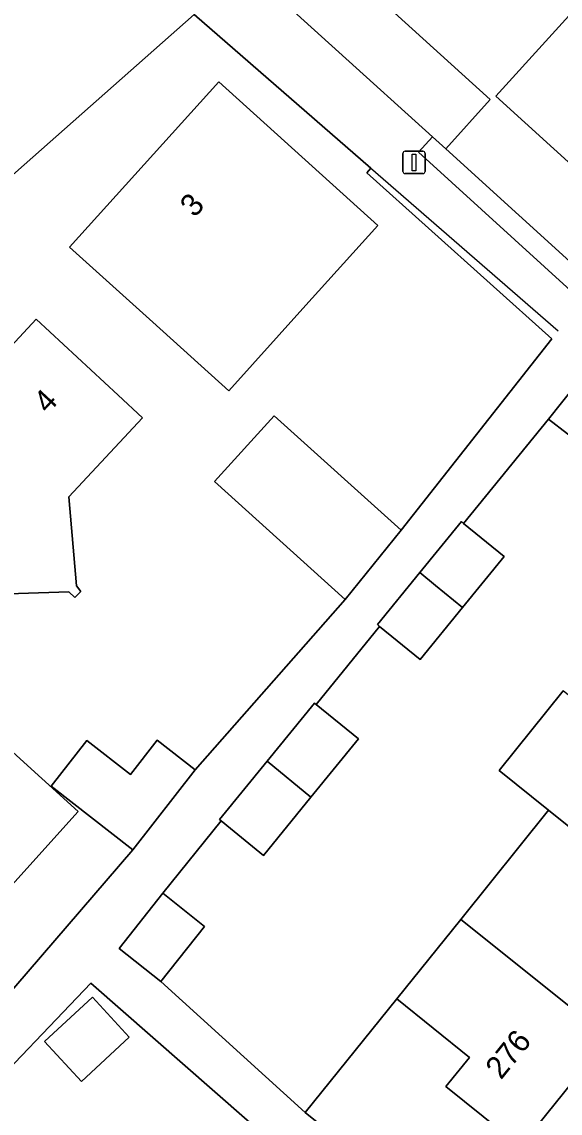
# Model space of a CAD drawing. Extents: x 158472 to 159562, y 388525 to 389606.
# Drawn here: x 158642.99 to 158667.04, y 388899.14 to 388947.87 of the extents above; entities that cross this region are included whole.
import ezdxf

# ---------------------------------------------------------------- set-up
doc = ezdxf.new("R2010")
doc.units = 0
for name, color, linetype in [('IMGEO_Erf', 7, 'Continuous'), ('IMGEO_Groenvoorziening', 7, 'Continuous'), ('IMGEO_Lichtmast', 7, 'Continuous'), ('IMGEO_Muur', 7, 'Continuous'), ('IMGEO_Pand', 7, 'Continuous'), ('IMGEO_Pand_nummerreeks', 7, 'Continuous'), ('IMGEO_Rijbaan_lokaal_open', 7, 'Continuous'), ('IMGEO_Voetpad_open', 7, 'Continuous')]:
    doc.layers.add(name, color=color, linetype=linetype)

msp = doc.modelspace()

# ---------------------------------------------------------------- linework, layer by layer
at = {"layer": 'IMGEO_Erf'}
for points in [[(158668.747, 388949.605), (158664.165, 388944.557), (158670.641, 388938.679), (158697.972, 388974.859)], [(158652.977, 388950.312), (158661.333, 388942.738), (158661.926, 388942.201), (158663.919, 388944.397), (158657.904, 388949.857)], [(158641.527, 388903.446), (158647.946, 388910.907), (158644.303, 388913.751), (158645.893, 388915.788), (158647.842, 388914.266), (158649.035, 388915.794), (158650.729, 388914.472), (158657.439, 388922.083), (158651.607, 388927.344), (158654.26, 388930.285), (158659.932, 388925.168), (158666.666, 388933.718), (158658.402, 388941.12), (158658.589, 388941.335), (158650.686, 388948.203), (158630.856, 388930.685)], [(158668.212, 388928.813), (158666.516, 388930.132), (158662.722, 388925.476), (158664.538, 388923.998), (158662.68, 388921.72), (158660.779, 388919.399), (158658.972, 388920.879), (158656.135, 388917.397), (158658.026, 388915.853), (158655.908, 388913.258), (158653.785, 388910.653), (158652.317, 388911.852), (158651.898, 388912.195), (158649.288, 388908.962), (158651.153, 388907.486), (158649.202, 388905.02), (158655.653, 388899.181), (158659.741, 388904.253), (158662.596, 388907.797), (158666.523, 388912.669), (158664.32, 388914.445), (158667.18, 388917.994)], [(158681.727, 388907.247), (158688.881, 388916.431), (158683.73, 388920.567), (158681.495, 388917.794), (158682.74, 388916.779), (158679.952, 388913.298), (158678.687, 388914.31), (158677.464, 388912.792), (158678.711, 388911.788), (158677.223, 388909.942), (158675.571, 388907.892), (158674.328, 388908.894), (158672.051, 388906.068), (158670.706, 388904.398), (158671.908, 388903.429), (158670.402, 388901.56), (158668.766, 388899.53), (158667.556, 388900.505), (158665.263, 388897.66), (158663.911, 388895.983), (158665.126, 388895.004), (158663.438, 388892.908), (158667.216, 388889.629)], [(158641.567, 388888.565), (158644.692, 388891.853), (158645.314, 388891.262), (158648.801, 388894.93), (158650.361, 388893.447), (158651.174, 388894.299), (158654.39, 388897.669), (158646.076, 388904.95), (158640.8, 388899.447)]]:
    msp.add_lwpolyline(points, dxfattribs=at)
for points in [[(158651.788, 388945.187), (158658.897, 388938.775), (158655.548, 388935.063), (158652.238, 388931.393), (158648.843, 388934.456), (158645.13, 388937.805)], [(158643.635, 388934.6), (158647.3, 388931.199), (158648.382, 388930.194), (158645.098, 388926.657), (158645.433, 388922.691), (158645.624, 388922.437), (158645.357, 388922.17), (158645.09, 388922.424), (158639.224, 388922.223), (158636.672, 388924.688), (158636.24, 388930.403), (158635.935, 388930.695), (158636.151, 388930.987), (158636.468, 388930.67), (158640.24, 388930.943)], [(158627.039, 388914.369), (158626.648, 388914.972), (158632.647, 388918.937), (158635.289, 388921.857), (158638.997, 388918.503), (158645.513, 388912.607), (158640.255, 388906.796), (158639.615, 388907.375), (158638.527, 388905.932), (158630.624, 388906.451), (158630.151, 388907.075), (158629.427, 388906.606), (158627.724, 388909.233), (158626.037, 388908.14), (158623.49, 388912.069)], [(158645.66, 388900.564), (158644.013, 388902.345), (158646.148, 388904.318), (158647.794, 388902.538)]]:
    msp.add_lwpolyline(points, close=True, dxfattribs=at)
at = {"layer": 'IMGEO_Groenvoorziening'}
msp.add_lwpolyline([(158661.926, 388942.201), (158661.333, 388942.738), (158660.708, 388942.048), (158667.83, 388935.583), (158668.457, 388936.273)], close=True, dxfattribs=at)
at = {"layer": 'IMGEO_Lichtmast'}
for p, q in [((158660.016, 388941.191), (158660.016, 388941.991)), ((158660.016, 388941.991), (158660.016, 388941.191)), ((158660.116, 388942.091), (158660.906, 388942.091)), ((158660.906, 388942.091), (158660.116, 388942.091)), ((158661.006, 388941.991), (158661.006, 388941.191)), ((158661.006, 388941.191), (158661.006, 388941.991)), ((158660.906, 388941.091), (158660.116, 388941.091)), ((158660.116, 388941.091), (158660.906, 388941.091))]:
    msp.add_line(p, q, dxfattribs=at)
msp.add_lwpolyline([(158660.436, 388941.966), (158660.586, 388941.966), (158660.586, 388941.216), (158660.436, 388941.216), (158660.436, 388941.966)], dxfattribs=at)
for centre, start, end in [((158660.116, 388941.991), 90, 180), ((158660.116, 388941.991), 90, 180), ((158660.906, 388941.991), 0, 90), ((158660.906, 388941.991), 360, 90), ((158660.116, 388941.191), 180, 270), ((158660.116, 388941.191), 180, 270), ((158660.906, 388941.191), 270, 0), ((158660.906, 388941.191), 270, 0)]:
    msp.add_arc(centre, 0.1, start, end, dxfattribs=at)
at = {"layer": 'IMGEO_Muur'}
msp.add_lwpolyline([(158658.566, 388941.355), (158666.945, 388934.072)], dxfattribs=at)
at = {"layer": 'IMGEO_Pand'}
for points in [[(158666.506, 388954.788), (158670.581, 388956.54), (158670.265, 388957.284), (158677.436, 388960.255), (158674.656, 388966.964), (158674.547, 388966.919), (158671.398, 388965.614), (158669.563, 388964.853), (158670.912, 388961.598), (158668.806, 388960.726), (158667.431, 388963.97), (158658.929, 388960.447), (158654.309, 388958.532), (158657.904, 388949.857), (158663.919, 388944.397), (158661.926, 388942.201), (158668.457, 388936.273), (158670.641, 388938.679), (158664.165, 388944.557), (158668.747, 388949.605)], [(158648.843, 388934.456), (158652.238, 388931.393), (158655.548, 388935.063), (158658.897, 388938.775), (158651.788, 388945.187), (158645.13, 388937.805)], [(158647.3, 388931.199), (158643.635, 388934.6), (158640.24, 388930.943), (158636.468, 388930.67), (158636.151, 388930.987), (158635.935, 388930.695), (158636.24, 388930.403), (158636.672, 388924.688), (158639.224, 388922.223), (158645.09, 388922.424), (158645.357, 388922.17), (158645.624, 388922.437), (158645.433, 388922.691), (158645.098, 388926.657), (158648.382, 388930.194)], [(158670.255, 388931.362), (158668.546, 388932.681), (158668.32, 388932.398), (158666.516, 388930.132), (158668.212, 388928.813)], [(158657.439, 388922.083), (158659.932, 388925.168), (158654.26, 388930.285), (158651.607, 388927.344)], [(158662.722, 388925.476), (158662.627, 388925.554), (158660.775, 388923.28), (158661.473, 388922.709), (158662.68, 388921.72), (158664.538, 388923.998)], [(158662.68, 388921.72), (158661.473, 388922.709), (158660.775, 388923.28), (158658.874, 388920.959), (158658.972, 388920.879), (158660.779, 388919.399)], [(158629.427, 388906.606), (158630.151, 388907.075), (158630.624, 388906.451), (158638.527, 388905.932), (158639.615, 388907.375), (158640.255, 388906.796), (158645.513, 388912.607), (158638.997, 388918.503), (158635.289, 388921.857), (158632.647, 388918.937), (158626.648, 388914.972), (158627.039, 388914.369), (158623.49, 388912.069), (158626.037, 388908.14), (158627.724, 388909.233)], [(158666.523, 388912.669), (158669.78, 388910.05), (158668.73, 388908.75), (158672.051, 388906.068), (158674.328, 388908.894), (158675.571, 388907.892), (158677.223, 388909.942), (158667.18, 388917.994), (158664.32, 388914.445)], [(158656.135, 388917.397), (158656.069, 388917.45), (158653.951, 388914.855), (158655.908, 388913.258), (158658.026, 388915.853)], [(158650.729, 388914.472), (158649.035, 388915.794), (158647.842, 388914.266), (158645.893, 388915.788), (158644.303, 388913.751), (158647.946, 388910.907)], [(158655.908, 388913.258), (158653.951, 388914.855), (158651.826, 388912.253), (158651.898, 388912.195), (158652.317, 388911.852), (158653.785, 388910.653)], [(158666.523, 388912.669), (158662.596, 388907.797), (158670.402, 388901.56), (158671.908, 388903.429), (158670.706, 388904.398), (158672.051, 388906.068), (158668.73, 388908.75), (158669.78, 388910.05)], [(158649.288, 388908.962), (158647.337, 388906.496), (158649.202, 388905.02), (158651.153, 388907.486)], [(158659.741, 388904.253), (158662.99, 388901.63), (158661.93, 388900.34), (158665.263, 388897.66), (158667.556, 388900.505), (158668.766, 388899.53), (158670.402, 388901.56), (158662.596, 388907.797)], [(158645.66, 388900.564), (158647.794, 388902.538), (158646.148, 388904.318), (158644.013, 388902.345)], [(158659.741, 388904.253), (158655.653, 388899.181), (158659.544, 388896.045), (158663.438, 388892.908), (158665.126, 388895.004), (158663.911, 388895.983), (158665.263, 388897.66), (158661.93, 388900.34), (158662.99, 388901.63)]]:
    msp.add_lwpolyline(points, close=True, dxfattribs=at)
at = {"layer": 'IMGEO_Rijbaan_lokaal_open'}
msp.add_lwpolyline([(158622.26, 388937.559), (158619.491, 388939.185), (158614.921, 388936.317), (158622.236, 388925.062), (158622.414, 388920.896), (158625.259, 388916.882), (158631.449, 388920.965), (158629.6, 388923.624), (158630.856, 388930.685), (158650.686, 388948.203), (158652.977, 388950.312), (158650.233, 388956.842), (158647.114, 388964.264), (158644.373, 388970.786), (158645.827, 388974.583), (158636.325, 388970.661), (158638.495, 388969.468), (158644.553, 388955.191), (158643.817, 388950.009), (158635.311, 388942.532), (158631.972, 388946.242)], close=True, dxfattribs=at)
at = {"layer": 'IMGEO_Voetpad_open'}
for points in [[(158697.972, 388974.859), (158670.641, 388938.679), (158668.457, 388936.273), (158667.83, 388935.583), (158660.708, 388942.048), (158661.333, 388942.738), (158652.977, 388950.312)], [(158650.686, 388948.203), (158658.589, 388941.335), (158658.402, 388941.12), (158666.666, 388933.718), (158659.932, 388925.168), (158657.439, 388922.083), (158650.729, 388914.472), (158647.946, 388910.907), (158641.527, 388903.446)], [(158659.544, 388896.045), (158655.653, 388899.181), (158649.202, 388905.02), (158647.337, 388906.496), (158649.288, 388908.962), (158651.898, 388912.195), (158651.826, 388912.253), (158653.951, 388914.855), (158656.069, 388917.45), (158656.135, 388917.397), (158658.972, 388920.879), (158658.874, 388920.959), (158660.775, 388923.28), (158662.627, 388925.554), (158662.722, 388925.476), (158666.516, 388930.132), (158668.32, 388932.398)], [(158640.8, 388899.447), (158646.076, 388904.95), (158654.39, 388897.669), (158658.018, 388894.207), (158661.636, 388890.756), (158665.374, 388887.512)]]:
    msp.add_lwpolyline(points, dxfattribs=at)

# ---------------------------------------------------------------- texts
at = {"layer": 'IMGEO_Pand_nummerreeks'}
for s, rotation, p in [('3', 47.952, (158650.71, 388939.095)), ('4', 47.1277, (158644.154, 388930.338)), ('276', 51.1291, (158664.399, 388900.604))]:
    msp.add_text(s, height=1, rotation=rotation, dxfattribs=at).set_placement(p)

doc.saveas('drawing.dxf')
